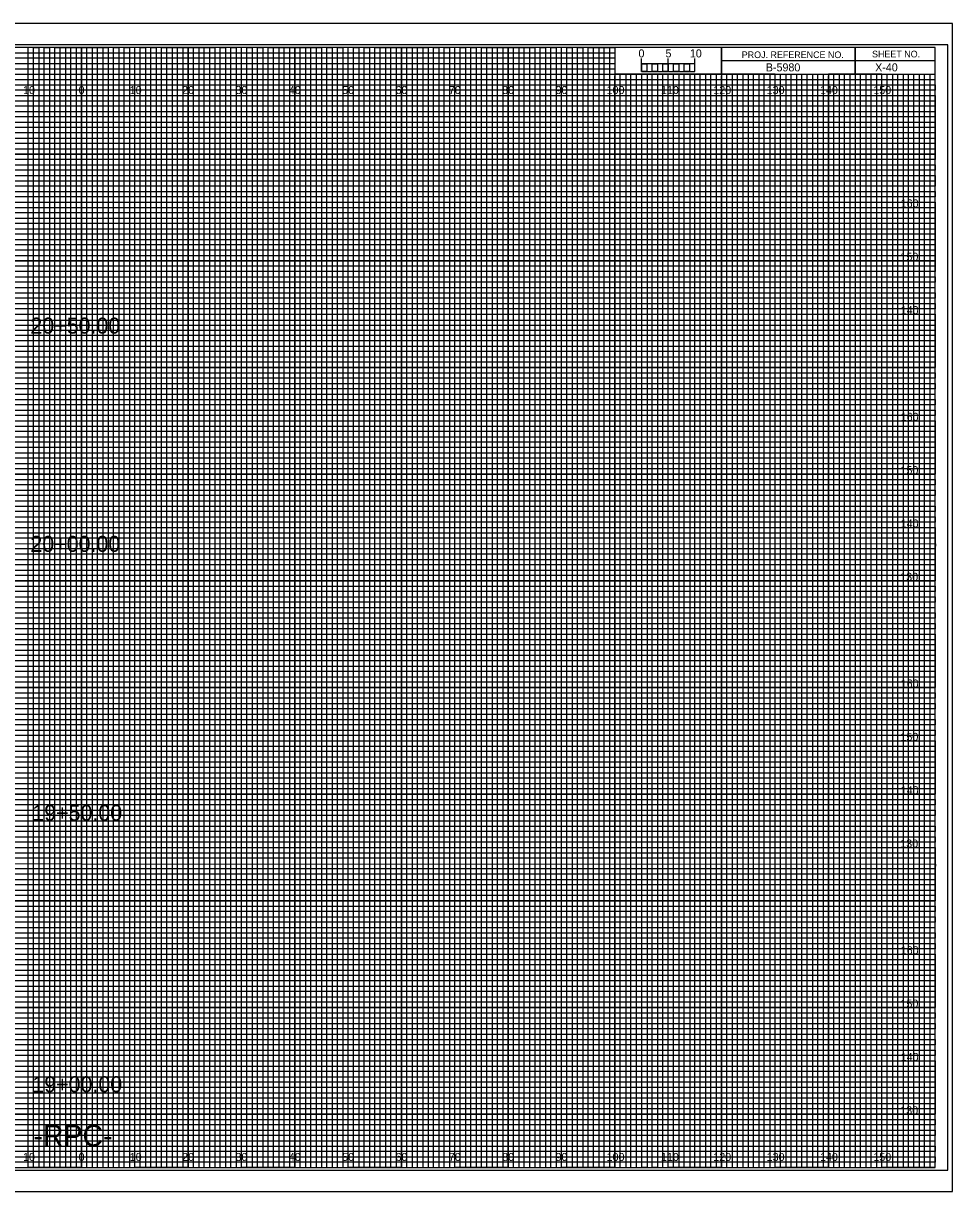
# Model space of a CAD drawing. Extents: x -13 to 323, y -5 to 874.
# Drawn here: x 149.1 to 323.3, y 435.5 to 654.5 of the extents above; entities that cross this region are included whole.
import ezdxf

# ---------------------------------------------------------------- set-up
doc = ezdxf.new("R2010")
doc.units = 0
for name, color, linetype in [('Exist Cross Section Cell', 7, 'Continuous'), ('Exist XS Center Line Elevation Label', 7, 'Continuous'), ('Exist XS Ground Line', 7, 'Continuous'), ('Prop CMT Conc Surface', 7, 'Continuous'), ('Prop CMT Concrete Structures', 7, 'Continuous'), ('Prop CMT Pvmt Course 1', 7, 'Continuous'), ('Prop CMT Pvmt Course 1 CG', 7, 'Continuous'), ('Prop CMT Pvmt Course 2', 7, 'Continuous'), ('Prop CMT Pvmt Course 3', 7, 'Continuous'), ('Prop CMT Pvmt Surface', 7, 'Continuous'), ('Prop CMT Pvmt Surface Shoulder', 7, 'Continuous'), ('Prop CMT Shld Paved Course 1', 7, 'Continuous'), ('Prop CMT Shld Paved Course 2', 7, 'Continuous'), ('Prop CMT Shld Paved Course 3', 7, 'Continuous'), ('Prop CMT Slope Grass', 7, 'Continuous'), ('Prop CMT Subgrade Earthwork', 7, 'Continuous'), ('Scratch_Level_1', 7, 'Continuous')]:
    doc.layers.add(name, color=color, linetype=linetype)

msp = doc.modelspace()

# ---------------------------------------------------------------- linework, layer by layer
at = {"layer": 'Exist XS Center Line Elevation Label'}
for points in [[(145, 440), (155, 440), (155, 650), (165, 650), (165, 440), (175, 440), (175, 650), (185, 650), (185, 440), (195, 440), (195, 650), (205, 650), (205, 440), (215, 440), (215, 650), (225, 650), (225, 440), (235, 440), (235, 650), (245, 650), (245, 440), (255, 440), (255, 650), (259.93, 650), (260, 650), (260, 645), (264.99, 645), (264.99, 440), (275, 440), (275, 645), (285, 645), (285, 440), (295, 440), (295, 645), (305, 645), (305, 440), (315, 440), (315, 645)], [(0, 645), (275, 645)], [(0, 625), (320, 625), (320, 635), (0, 635)], [(0, 605), (320, 605), (320, 615), (0, 615)], [(0, 585), (320, 585), (320, 595), (0, 595)], [(0, 565), (320, 565), (320, 575), (0, 575)], [(0, 545), (320, 545), (320, 555), (0, 555)], [(0, 525), (320, 525), (320, 535), (0, 535)], [(0, 505), (320, 505), (320, 515), (0, 515)], [(0, 485), (320, 485), (320, 495), (0, 495)], [(0, 465), (320, 465), (320, 475), (0, 475)], [(0, 445), (320, 445), (320, 455), (0, 455)]]:
    msp.add_lwpolyline(points, dxfattribs=at)
at = {"layer": 'Exist XS Ground Line'}
for p, q in [((150, 650), (140, 650)), ((150, 440), (150, 650)), ((170, 650), (160, 650)), ((160, 650), (160, 440)), ((170, 440), (170, 650)), ((190, 650), (180, 650)), ((180, 650), (180, 440)), ((190, 440), (190, 650)), ((210, 650), (200, 650)), ((200, 650), (200, 440)), ((210, 440), (210, 650)), ((230, 650), (220, 650)), ((220, 650), (220, 440)), ((230, 440), (230, 650)), ((250, 650), (240, 650)), ((240, 650), (240, 440)), ((250, 440), (250, 650)), ((260, 650), (260, 440)), ((270, 440), (270, 645)), ((290, 645), (280, 645)), ((280, 645), (280, 440)), ((290, 440), (290, 645)), ((310, 645), (300, 645)), ((300, 645), (300, 440)), ((310, 440), (310, 645)), ((160, 440), (150, 440)), ((180, 440), (170, 440)), ((200, 440), (190, 440)), ((220, 440), (210, 440)), ((240, 440), (230, 440)), ((260, 440), (250, 440)), ((280, 440), (270, 440)), ((300, 440), (290, 440)), ((320, 440), (310, 440)), ((320, 440), (320, 440))]:
    msp.add_line(p, q, dxfattribs=at)
for points in [[(0, 640), (320, 640), (320, 630), (0, 630)], [(0, 620), (320, 620), (320, 610), (0, 610)], [(0, 600), (320, 600), (320, 590), (0, 590)], [(0, 580), (320, 580), (320, 570), (0, 570)], [(0, 560), (320, 560), (320, 550), (0, 550)], [(0, 540), (320, 540), (320, 530), (0, 530)], [(0, 520), (320, 520), (320, 510), (0, 510)], [(0, 500), (320, 500), (320, 490), (0, 490)], [(0, 480), (320, 480), (320, 470), (0, 470)], [(0, 460), (320, 460), (320, 450), (0, 450)]]:
    msp.add_lwpolyline(points, dxfattribs=at)
at = {"layer": 'Prop CMT Pvmt Course 2'}
for p, q in [((265, 645.49), (265, 647.9)), ((265, 646.9), (265, 647.9)), ((270, 645.49), (270, 647.9)), ((275, 645.49), (275, 647.9)), ((275, 646.9), (275, 647.9))]:
    msp.add_line(p, q, dxfattribs=at)
for points in [[(275, 646.9), (265, 646.9), (265, 645.49), (275, 645.49)], [(265, 646.9), (266, 646.9), (266, 645.49), (265, 645.49)], [(267, 646.9), (268, 646.9), (268, 645.49), (267, 645.49)], [(269, 646.9), (270, 646.9), (270, 645.49), (269, 645.49)], [(271, 646.9), (272, 646.9), (272, 645.49), (271, 645.49)], [(273, 646.9), (274, 646.9), (274, 645.49), (273, 645.49)]]:
    msp.add_lwpolyline(points, close=True, dxfattribs=at)
at = {"layer": 'Prop CMT Pvmt Course 3'}
msp.add_lwpolyline([(-13.4, 435.5), (323.3, 435.5), (323.3, 654.5), (-13.4, 654.5)], close=True, dxfattribs=at)
at = {"layer": 'Prop CMT Pvmt Surface'}
for p, q in [((150, 440), (150, 650)), ((160, 440), (160, 650)), ((170, 440), (170, 650)), ((180, 440), (180, 650)), ((190, 440), (190, 650)), ((200, 440), (200, 650)), ((210, 440), (210, 650)), ((220, 440), (220, 650)), ((230, 440), (230, 650)), ((240, 440), (240, 650)), ((250, 440), (250, 650)), ((260, 440), (260, 644.69)), ((270, 440), (270, 644.69)), ((280, 440), (280, 644.69)), ((290, 440), (290, 644.69)), ((300, 440), (300, 644.69)), ((310, 440), (310, 644.69)), ((0, 640), (320, 640)), ((0, 630), (320, 630)), ((0, 620), (320, 620)), ((0, 610), (320, 610)), ((0, 600), (320, 600)), ((0, 590), (320, 590)), ((0, 580), (320, 580)), ((0, 570), (320, 570)), ((0, 560), (320, 560)), ((0, 550), (320, 550)), ((0, 540), (320, 540)), ((0, 530), (320, 530)), ((0, 520), (320, 520)), ((0, 510), (320, 510)), ((0, 500), (320, 500)), ((0, 490), (320, 490)), ((0, 480), (320, 480)), ((0, 470), (320, 470)), ((0, 460), (320, 460)), ((0, 450), (320, 450))]:
    msp.add_line(p, q, dxfattribs=at)
at = {"layer": 'Prop CMT Pvmt Surface Shoulder'}
for p, q in [((323.3, 654.5), (-13.4, 654.5)), ((-13.4, 435.5), (323.3, 435.5))]:
    msp.add_line(p, q, dxfattribs=at)
at = {"layer": 'Prop CMT Shld Paved Course 1'}
for p, q in [((0, 649), (260, 649)), ((260, 649), (260, 647.98)), ((260, 647.98), (0, 647.98)), ((0, 647), (260, 647)), ((260, 647), (260, 645.89)), ((260, 645.89), (0, 645.89)), ((0, 644), (320, 644))]:
    msp.add_line(p, q, dxfattribs=at)
for points in [[(0, 643), (270, 643), (320, 643), (320, 642), (0, 642)], [(0, 641), (320, 641), (320, 639), (0, 639)], [(0, 638), (320, 638), (320, 637), (0, 636.98)], [(0, 636), (320, 636), (320, 634), (0, 634)], [(0, 633), (320, 633), (320, 632), (0, 632)], [(0, 631), (320, 631), (320, 629), (0, 629)], [(0, 628), (320, 628), (320, 627), (0, 627)], [(0, 626), (320, 626), (320, 624), (0, 624)], [(0, 623), (320, 623), (320, 622), (0, 622)], [(0, 621), (320, 621), (320, 619), (0, 619)], [(0, 618), (320, 618), (320, 617), (0, 617)], [(0, 616), (320, 616), (320, 613.95), (320, 613), (320, 612), (0, 612)], [(0, 614), (320, 614), (320, 613), (0, 613)], [(0, 611), (320, 611), (320, 609), (0, 609.03)], [(0, 609.03), (320, 609), (320, 608), (0, 608)], [(0, 607), (320, 607), (320, 606), (0, 606)], [(0, 604), (320, 604), (320, 603), (0, 603)], [(0, 602), (320, 602), (320, 601), (0, 601)], [(-0.07, 598.89), (320, 598.89), (320, 597.88), (-0.07, 597.88)], [(0, 597), (320, 597), (320, 596), (0, 596)], [(0, 594), (320, 594), (320, 593), (0, 593)], [(0, 592), (320, 592), (320, 591), (0, 591)], [(0, 589), (320, 589), (320, 588), (0, 588)], [(0, 587), (320, 587), (320, 586), (0, 586)], [(0, 584), (320, 584), (320, 583), (0, 583)], [(0, 582), (320, 582), (320, 581), (0, 581)], [(0, 579), (320, 579), (319.99, 577.98), (0, 578)], [(0, 577), (320, 577), (320, 576), (0, 576)], [(0, 574), (320, 574), (320, 573), (0, 573)], [(0, 572), (320, 572), (320, 571), (0, 571)], [(0, 569), (320, 569), (320, 568), (0, 568)], [(0, 567), (320, 567), (320, 566), (0, 566)], [(0, 564), (320, 564), (320, 563), (0, 563)], [(0, 562), (320, 562), (320, 561), (0, 561)], [(0, 559), (320, 559), (320, 558), (0, 558)], [(0, 556.99), (320.07, 556.91), (320, 556), (0, 556)], [(0, 554), (320, 554), (320, 553), (0, 553)], [(0, 552), (320, 552), (320, 551), (0, 551)], [(0, 549), (320, 549), (320, 548), (0, 548)], [(0, 547), (320, 547), (320, 546), (0, 546)], [(0, 544), (320, 544), (320, 543), (0, 543)], [(0, 542), (320, 542), (320, 541), (0, 541)], [(0, 539), (320, 539), (320, 538), (0, 538)], [(0, 537), (320, 537), (320, 536), (0, 536)], [(0, 534), (320, 534), (320, 533), (0, 533)], [(0, 532), (320, 532), (320, 531), (0, 531)], [(0, 529), (320, 529), (320, 528), (0, 528)], [(0, 527), (320, 527), (320, 526), (0, 526)], [(0, 524), (320, 524), (320, 523), (0, 523)], [(0, 522), (320, 522), (320, 521), (0, 521)], [(0, 519), (320, 519), (319.99, 517.98), (0, 518)], [(0, 517), (320, 517), (320, 516), (0, 516)], [(0, 514), (320, 514), (320, 513), (0, 513)], [(0, 512), (320, 512), (320, 511), (0, 511)], [(0, 509), (320, 509), (320, 508), (0, 508)], [(0, 507), (320, 507), (320, 506), (0, 506)], [(0, 504), (320, 504), (320, 503), (0, 503)], [(0, 502), (320, 502), (320, 501), (0, 501)], [(0, 499), (320, 499), (320, 498), (0, 498)], [(0, 496.99), (320.07, 496.91), (320, 496), (0, 496)], [(0, 494), (320, 494), (320, 493), (0, 493)], [(0, 492), (320, 492), (320, 491), (0, 491)], [(0, 489), (320, 489), (320, 488), (0, 488)], [(0, 487), (320, 487), (320, 486), (0, 486)], [(0, 484), (320, 484), (320, 483), (0, 483)], [(0, 482), (320, 482), (320, 481), (0, 481)], [(0, 479), (320, 479), (320, 478), (0, 478)], [(0, 477), (320, 477), (320, 476), (0, 476)], [(0, 474), (320, 474), (320, 473), (0, 473)], [(0, 472), (320, 472), (320, 471), (0, 471)], [(0, 469), (320, 469), (320, 468), (0, 468)], [(0, 467), (320, 467), (320, 466), (0, 466)], [(0, 464), (320, 464), (320, 463), (0, 463)], [(0, 462), (320, 462), (320, 461), (0, 461)], [(0, 459), (320, 459), (320, 458), (0, 458)], [(0, 457), (320, 457), (320, 456), (0, 456)], [(0, 454), (320, 454), (320, 453), (0, 453)], [(0, 452), (320, 452), (320, 451), (0, 451)], [(0, 449), (320, 449), (320, 448), (0, 448)], [(0, 447), (320, 447), (320, 446), (0, 446)], [(0, 444), (320, 444), (320, 443), (0, 443)], [(0, 442), (320, 442), (320, 441), (0, 441)]]:
    msp.add_lwpolyline(points, dxfattribs=at)
at = {"layer": 'Prop CMT Shld Paved Course 2'}
for p, q in [((305, 650), (305, 645)), ((305, 645), (305, 650)), ((280, 647.5), (280, 645)), ((320, 647.49), (280, 647.49)), ((280, 645), (320, 645))]:
    msp.add_line(p, q, dxfattribs=at)
for points in [[(320, 650), (0, 650), (0, 440), (320, 440)], [(280, 650), (260, 650), (260, 645.03), (280, 645.03)], [(320, 650), (280, 650), (280, 645), (320, 645)]]:
    msp.add_lwpolyline(points, close=True, dxfattribs=at)
at = {"layer": 'Prop CMT Shld Paved Course 3'}
for p, q in [((267, 645), (266.01, 645)), ((266.01, 645), (266.01, 440)), ((267, 440), (267, 645)), ((269, 645), (268, 645)), ((268, 645), (268, 440)), ((269, 440), (269, 645)), ((266.01, 440), (265, 440)), ((268, 440), (267, 440))]:
    msp.add_line(p, q, dxfattribs=at)
for points in [[(150, 440), (151, 440), (151, 650), (152, 650), (152, 440)], [(152, 440), (153, 440), (153, 650), (154, 650), (154, 440)], [(155, 440), (156, 440), (156, 650), (157, 650), (157, 440)], [(157, 440), (158, 440), (158, 650), (159, 650), (159, 440)], [(160, 440), (161, 440), (161, 650), (162, 650), (162, 440)], [(162, 440), (163, 440), (163, 650), (164, 650), (164, 440)], [(165, 440), (166, 440), (166, 650), (167, 650), (167, 440)], [(167, 440), (168, 440), (168, 650), (169, 650), (169, 440)], [(170, 440), (171, 440), (171, 650), (172, 650), (172, 440)], [(172, 440), (173, 440), (173, 650), (174, 650), (174, 440)], [(175, 440), (176, 440), (176, 650), (177, 650), (177, 440)], [(177, 440), (178, 440), (178, 650), (179, 650), (179, 440)], [(180, 440), (181, 440), (181, 650), (182, 650), (182, 440)], [(182, 440), (183, 440), (183, 650), (184, 650), (184, 440)], [(185, 440), (186, 440), (186, 650), (187, 650), (187, 440)], [(187, 440), (188, 440), (188, 650), (189, 650), (189, 440)], [(190, 440), (191, 440), (191, 650), (192, 650), (192, 440)], [(192, 440), (193, 440), (193, 650), (194, 650), (194, 440)], [(195, 440), (196, 440), (196, 650), (197, 650), (197, 440)], [(197, 440), (198, 440), (198, 650), (199, 650), (199, 440)], [(200, 440), (201, 440), (201, 650), (202, 650), (202, 440)], [(202, 440), (203, 440), (203, 650), (204, 650), (204, 440)], [(205, 440), (206, 440), (206, 650), (207, 650), (207, 440)], [(207, 440), (208, 440), (208, 650), (209, 650), (209, 440)], [(210, 440), (211, 440), (211, 650), (212, 650), (212, 440)], [(212, 440), (213, 440), (213, 650), (214, 650), (214, 440)], [(215, 440), (216, 440), (216, 650), (217, 650), (217, 440)], [(217, 440), (218, 440), (218, 650), (219, 650), (219, 440)], [(220, 440), (221, 440), (221, 650), (222, 650), (222, 440)], [(222, 440), (223, 440), (223, 650), (224, 650), (224, 440)], [(225, 440), (226, 440), (226, 650), (227, 650), (227, 440)], [(227, 440), (228, 440), (228, 650), (229, 650), (229, 440)], [(230, 440), (231, 440), (231, 650), (232, 650), (232, 440)], [(232, 440), (233, 440), (233, 650), (234, 650), (234, 440)], [(235, 440), (236, 440), (236, 650), (237, 650), (237, 440)], [(237, 440), (238, 440), (238, 650), (239, 650), (239, 440)], [(240, 440), (241, 440), (241, 650), (242, 650), (242, 440)], [(242, 440), (243, 440), (243, 650), (244, 650), (244, 440)], [(245, 440), (246, 440), (246, 650), (247, 650), (247, 440)], [(247, 440), (248, 440), (248, 650), (249, 650), (249, 440)], [(250, 440), (251, 440), (251, 650), (252, 650), (252, 440)], [(252, 440), (253, 440), (253, 650), (254, 650), (254, 440)], [(255, 440), (256, 440), (256, 650), (257, 650), (257, 440)], [(257, 440), (258, 440), (258, 650), (259, 650), (259, 440)], [(260, 440), (261, 440), (261, 645), (262.02, 645), (262.02, 440)], [(262, 440), (263, 440), (263, 645), (263.99, 645), (263.99, 440)], [(270, 440), (270.98, 440), (270.98, 645), (272, 645), (272, 440)], [(272, 440), (273, 440), (273, 645), (274.05, 645), (274.05, 440)], [(275, 440), (276, 440), (276, 645), (277, 645), (277, 440)], [(277, 440), (278, 440), (278, 645), (279, 645), (279, 440)], [(280, 440), (281, 440), (281, 645), (282, 645), (282, 440)], [(282, 440), (283, 440), (283, 645), (284, 645), (284, 440)], [(285, 440), (286, 440), (286, 645), (287, 645), (287, 440)], [(287, 440), (288, 440), (288, 645), (289, 645), (289, 440)], [(290, 440), (291, 440), (291, 645), (292, 645), (292, 440)], [(292, 440), (293, 440), (293, 645), (294, 645), (294, 440)], [(295, 440), (296, 440), (296, 645), (297, 645), (297, 440)], [(297, 440), (298, 440), (298, 645), (299, 645), (299, 440)], [(300, 440), (301, 440), (301, 645), (302, 645), (302, 440)], [(302, 440), (303, 440), (303, 645), (304, 645), (304, 440)], [(305, 440), (306, 440), (306, 645), (307, 645), (307, 440)], [(307, 440), (308, 440), (308, 645), (309, 645), (309, 440)], [(310, 440), (311, 440), (311, 645), (312, 645), (312, 440)], [(312, 440), (313, 440), (313, 645), (314, 645), (314, 440)], [(315, 440), (316, 440), (316, 645), (317, 645), (317, 440)], [(317, 440), (318, 440), (318, 645), (319, 645), (319, 440)]]:
    msp.add_lwpolyline(points, dxfattribs=at)
at = {"layer": 'Prop CMT Subgrade Earthwork'}
msp.add_lwpolyline([(-10.8, 439.5), (322.4, 439.5), (322.4, 650.5), (-10.8, 650.5)], close=True, dxfattribs=at)

# ---------------------------------------------------------------- texts
at = {"layer": 'Exist Cross Section Cell'}
for s, p in [('10', (149.04, 641.25)), ('0', (159.45, 641.25)), ('0', (159.45, 641.25)), ('10', (169.04, 641.25)), ('20', (178.86, 641.25)), ('30', (188.86, 641.25)), ('40', (198.86, 641.25)), ('50', (208.86, 641.25)), ('60', (218.86, 641.25)), ('70', (228.86, 641.25)), ('80', (238.86, 641.25)), ('90', (248.86, 641.25)), ('100', (258.44, 641.25)), ('110', (268.62, 641.25)), ('120', (278.44, 641.25)), ('130', (288.44, 641.25)), ('140', (298.44, 641.25)), ('150', (308.44, 641.25)), ('10', (149.04, 441.25)), ('0', (159.45, 441.25)), ('0', (159.45, 441.25)), ('10', (169.04, 441.25)), ('20', (178.86, 441.25)), ('30', (188.86, 441.25)), ('40', (198.86, 441.25)), ('50', (208.86, 441.25)), ('60', (218.86, 441.25)), ('70', (228.86, 441.25)), ('80', (238.86, 441.25)), ('90', (248.86, 441.25)), ('100', (258.44, 441.25)), ('110', (268.62, 441.25)), ('120', (278.44, 441.25)), ('130', (288.44, 441.25)), ('140', (298.44, 441.25)), ('150', (308.44, 441.25))]:
    msp.add_text(s, height=1.5, dxfattribs=at).set_placement(p)
at = {"layer": 'Prop CMT Conc Surface'}
for s, p in [('5', (269.47, 648.12)), ('10', (274.04, 648.12))]:
    msp.add_text(s, height=1.5, dxfattribs=at).set_placement(p)
at = {"layer": 'Prop CMT Concrete Structures'}
msp.add_text('B-5980', height=1.5, dxfattribs=at).set_placement((288.28, 645.5))
at = {"layer": 'Prop CMT Pvmt Course 1'}
for s, p in [('160', (313.57, 620)), ('150', (313.52, 610)), ('140', (313.57, 600)), ('160', (313.57, 580)), ('150', (313.52, 570)), ('140', (313.57, 560)), ('130', (313.49, 550)), ('160', (313.57, 530)), ('150', (313.52, 520)), ('140', (313.57, 510)), ('130', (313.49, 500)), ('160', (313.57, 480)), ('150', (313.52, 470)), ('140', (313.57, 460)), ('130', (313.49, 450))]:
    msp.add_text(s, height=1.5, dxfattribs=at).set_placement(p)
at = {"layer": 'Prop CMT Pvmt Course 1 CG'}
msp.add_text('-RPC-', height=4, dxfattribs=at).set_placement((150.97, 444))
at = {"layer": 'Prop CMT Pvmt Course 2'}
msp.add_text('0', height=1.5, dxfattribs=at).set_placement((264.41, 648.12))
at = {"layer": 'Prop CMT Shld Paved Course 2'}
for s, p in [('PROJ. REFERENCE NO.', (283.77, 647.99)), ('SHEET NO.', (308.19, 648.12))]:
    msp.add_text(s, height=1.25, dxfattribs=at).set_placement(p)
at = {"layer": 'Prop CMT Slope Grass'}
for s, p in [('20+50.00', (150.41, 596.34)), ('20+00.00', (150.41, 555.43)), ('19+50.00', (150.77, 505.02)), ('19+00.00', (150.77, 454.13))]:
    msp.add_text(s, height=3, dxfattribs=at).set_placement(p)
at = {"layer": 'Scratch_Level_1'}
msp.add_text('X-40', height=1.5, dxfattribs=at).set_placement((308.77, 645.5))

doc.saveas('drawing.dxf')
